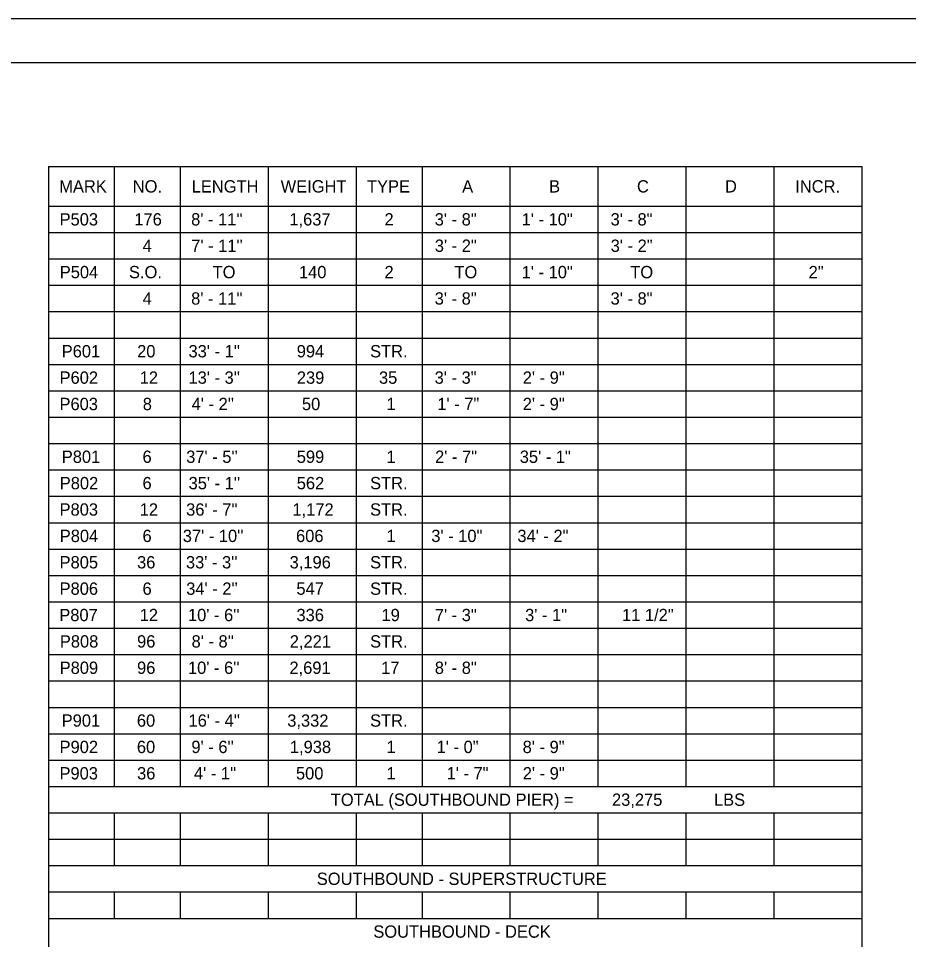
# Model space of a CAD drawing. Extents: x 1485751 to 1485785, y 230696.6 to 230718.6.
# Drawn here: x 1485763.32 to 1485773.44, y 230708.16 to 230718.64 of the extents above; entities that cross this region are included whole.
import ezdxf

# ---------------------------------------------------------------- set-up
doc = ezdxf.new("R2010")
doc.units = 0
for name, color, linetype in [('SH_Border', 7, 'Continuous'), ('SH_Cut_Line', 7, 'Continuous'), ('TX_P_Misc', 7, 'Continuous')]:
    doc.layers.add(name, color=color, linetype=linetype)

msp = doc.modelspace()

# ---------------------------------------------------------------- linework, layer by layer
at = {"layer": 'SH_Border'}
msp.add_lwpolyline([(1485753.033, 230718.141), (1485784.533, 230718.141), (1485784.533, 230697.141), (1485753.033, 230697.141)], close=True, dxfattribs=at)
at = {"layer": 'SH_Cut_Line'}
msp.add_lwpolyline([(1485751.033, 230718.641), (1485785.033, 230718.641), (1485785.033, 230696.641), (1485751.033, 230696.641)], close=True, dxfattribs=at)
at = {"layer": 'TX_P_Misc'}
for p, q in [((1485763.658, 230716.956), (1485772.908, 230716.956)), ((1485763.658, 230716.956), (1485763.658, 230698.806)), ((1485764.408, 230716.956), (1485764.408, 230709.906)), ((1485765.158, 230716.956), (1485765.158, 230709.906)), ((1485766.158, 230716.956), (1485766.158, 230709.906)), ((1485767.158, 230716.956), (1485767.158, 230709.906)), ((1485767.908, 230716.956), (1485767.908, 230709.906)), ((1485768.908, 230716.956), (1485768.908, 230709.906)), ((1485769.908, 230716.956), (1485769.908, 230709.906)), ((1485770.908, 230716.956), (1485770.908, 230709.906)), ((1485771.908, 230716.956), (1485771.908, 230709.906)), ((1485772.908, 230716.956), (1485772.908, 230698.806)), ((1485763.658, 230716.506), (1485772.908, 230716.506)), ((1485763.658, 230716.206), (1485772.908, 230716.206)), ((1485763.658, 230715.906), (1485772.908, 230715.906)), ((1485763.658, 230715.606), (1485772.908, 230715.606)), ((1485763.658, 230715.306), (1485772.908, 230715.306)), ((1485763.658, 230715.006), (1485772.908, 230715.006)), ((1485763.658, 230714.706), (1485772.908, 230714.706)), ((1485763.658, 230714.406), (1485772.908, 230714.406)), ((1485763.658, 230714.106), (1485772.908, 230714.106)), ((1485763.658, 230713.806), (1485772.908, 230713.806)), ((1485763.658, 230713.506), (1485772.908, 230713.506)), ((1485763.658, 230713.206), (1485772.908, 230713.206)), ((1485763.658, 230712.906), (1485772.908, 230712.906)), ((1485763.658, 230712.606), (1485772.908, 230712.606)), ((1485763.658, 230712.306), (1485772.908, 230712.306)), ((1485763.658, 230712.006), (1485772.908, 230712.006)), ((1485763.658, 230711.706), (1485772.908, 230711.706)), ((1485763.658, 230711.406), (1485772.908, 230711.406)), ((1485763.658, 230711.106), (1485772.908, 230711.106)), ((1485763.658, 230710.806), (1485772.908, 230710.806)), ((1485763.658, 230710.506), (1485772.908, 230710.506)), ((1485763.658, 230710.206), (1485772.908, 230710.206)), ((1485763.658, 230709.906), (1485772.908, 230709.906)), ((1485763.658, 230709.606), (1485772.908, 230709.606)), ((1485764.408, 230709.606), (1485764.408, 230709.006)), ((1485765.158, 230709.606), (1485765.158, 230709.006)), ((1485766.158, 230709.606), (1485766.158, 230709.006)), ((1485767.158, 230709.606), (1485767.158, 230709.006)), ((1485767.908, 230709.606), (1485767.908, 230709.006)), ((1485768.908, 230709.606), (1485768.908, 230709.006)), ((1485769.908, 230709.606), (1485769.908, 230709.006)), ((1485770.908, 230709.606), (1485770.908, 230709.006)), ((1485771.908, 230709.606), (1485771.908, 230709.006)), ((1485763.658, 230709.306), (1485772.908, 230709.306)), ((1485763.658, 230709.006), (1485772.908, 230709.006)), ((1485763.658, 230708.706), (1485772.908, 230708.706)), ((1485764.408, 230708.706), (1485764.408, 230708.406)), ((1485765.158, 230708.706), (1485765.158, 230708.406)), ((1485766.158, 230708.706), (1485766.158, 230708.406)), ((1485767.158, 230708.706), (1485767.158, 230708.406)), ((1485767.908, 230708.706), (1485767.908, 230708.406)), ((1485768.908, 230708.706), (1485768.908, 230708.406)), ((1485769.908, 230708.706), (1485769.908, 230708.406)), ((1485770.908, 230708.706), (1485770.908, 230708.406)), ((1485771.908, 230708.706), (1485771.908, 230708.406)), ((1485763.658, 230708.406), (1485772.908, 230708.406))]:
    msp.add_line(p, q, dxfattribs=at)

# ---------------------------------------------------------------- texts
for s, p in [('MARK', (1485763.782, 230716.661)), ('NO.', (1485764.618, 230716.661)), ('LENGTH', (1485765.288, 230716.661)), ('WEIGHT', (1485766.3, 230716.661)), ('TYPE', (1485767.282, 230716.661)), ('A', (1485768.364, 230716.661)), ('B', (1485769.353, 230716.661)), ('C', (1485770.352, 230716.661)), ('D', (1485771.353, 230716.661)), ('INCR.', (1485772.152, 230716.661)), ('P503', (1485763.786, 230716.286)), ('176', (1485764.636, 230716.286)), ("8' - 11''", (1485765.282, 230716.286)), ('1,637', (1485766.399, 230716.286)), ('2', (1485767.481, 230716.286)), ('3\' - 8"', (1485768.052, 230716.286)), ('1\' - 10"', (1485769.041, 230716.286)), ('3\' - 8"', (1485770.052, 230716.286)), ('4', (1485764.731, 230715.986)), ("7' - 11''", (1485765.283, 230715.986)), ('3\' - 2"', (1485768.053, 230715.986)), ('3\' - 2"', (1485770.053, 230715.986)), ('P504', (1485763.788, 230715.686)), ('S.O.', (1485764.575, 230715.686)), ('TO', (1485765.526, 230715.686)), ('140', (1485766.508, 230715.686)), ('2', (1485767.481, 230715.686)), ('TO', (1485768.276, 230715.686)), ('1\' - 10"', (1485769.041, 230715.686)), ('TO', (1485770.276, 230715.686)), (' 2"', (1485772.252, 230715.686)), ('4', (1485764.731, 230715.386)), ("8' - 11''", (1485765.282, 230715.386)), ('3\' - 8"', (1485768.052, 230715.386)), ('3\' - 8"', (1485770.052, 230715.386)), ('P601', (1485763.81, 230714.786)), ('20', (1485764.668, 230714.786)), ("33' - 1''", (1485765.252, 230714.786)), ('994', (1485766.483, 230714.786)), ('STR.', (1485767.317, 230714.786)), ('P602', (1485763.786, 230714.486)), ('12', (1485764.697, 230714.486)), ("13' - 3''", (1485765.252, 230714.486)), ('239', (1485766.484, 230714.486)), ('35', (1485767.418, 230714.486)), ('3\' - 3"', (1485768.051, 230714.486)), ('2\' - 9"', (1485769.053, 230714.486)), ('P603', (1485763.785, 230714.186)), ('8', (1485764.732, 230714.186)), ("4' - 2''", (1485765.288, 230714.186)), ('50', (1485766.542, 230714.186)), ('1', (1485767.504, 230714.186)), ('1\' - 7"', (1485768.082, 230714.186)), ('2\' - 9"', (1485769.053, 230714.186)), ('P801', (1485763.811, 230713.586)), ('6', (1485764.729, 230713.586)), ("37' - 5''", (1485765.226, 230713.586)), ('599', (1485766.483, 230713.586)), ('1', (1485767.504, 230713.586)), ('2\' - 7"', (1485768.056, 230713.586)), ('35\' - 1"', (1485769.019, 230713.586)), ('P802', (1485763.788, 230713.286)), ('6', (1485764.729, 230713.286)), ("35' - 1''", (1485765.253, 230713.286)), ('562', (1485766.483, 230713.286)), ('STR.', (1485767.317, 230713.286)), ('P803', (1485763.786, 230712.986)), ('12', (1485764.697, 230712.986)), ("36' - 7''", (1485765.225, 230712.986)), ('1,172', (1485766.434, 230712.986)), ('STR.', (1485767.317, 230712.986)), ('P804', (1485763.788, 230712.686)), ('6', (1485764.729, 230712.686)), ("37' - 10''", (1485765.187, 230712.686)), ('606', (1485766.475, 230712.686)), ('1', (1485767.504, 230712.686)), ('3\' - 10"', (1485768.013, 230712.686)), ('34\' - 2"', (1485768.992, 230712.686)), ('P805', (1485763.786, 230712.386)), ('36', (1485764.667, 230712.386)), ("33' - 3''", (1485765.223, 230712.386)), ('3,196', (1485766.402, 230712.386)), ('STR.', (1485767.317, 230712.386)), ('P806', (1485763.786, 230712.086)), ('6', (1485764.729, 230712.086)), ("34' - 2''", (1485765.226, 230712.086)), ('547', (1485766.479, 230712.086)), ('STR.', (1485767.317, 230712.086)), ('P807', (1485763.783, 230711.786)), ('12', (1485764.697, 230711.786)), ("10' - 6''", (1485765.246, 230711.786)), ('336', (1485766.48, 230711.786)), ('19', (1485767.447, 230711.786)), ('7\' - 3"', (1485768.053, 230711.786)), ('3\' - 1"', (1485769.08, 230711.786)), (' 11 1/2"', (1485770.13, 230711.786)), ('P808', (1485763.789, 230711.486)), ('96', (1485764.667, 230711.486)), ("8' - 8''", (1485765.287, 230711.486)), ('2,221', (1485766.404, 230711.486)), ('STR.', (1485767.317, 230711.486)), ('P809', (1485763.787, 230711.186)), ('96', (1485764.667, 230711.186)), ("10' - 6''", (1485765.246, 230711.186)), ('2,691', (1485766.4, 230711.186)), ('17', (1485767.443, 230711.186)), ('8\' - 8"', (1485768.053, 230711.186)), ('P901', (1485763.81, 230710.586)), ('60', (1485764.665, 230710.586)), ("16' - 4''", (1485765.252, 230710.586)), ('3,332', (1485766.375, 230710.586)), ('STR.', (1485767.317, 230710.586)), ('P902', (1485763.786, 230710.286)), ('60', (1485764.665, 230710.286)), ("9' - 6''", (1485765.285, 230710.286)), ('1,938', (1485766.405, 230710.286)), ('1', (1485767.504, 230710.286)), ('1\' - 0"', (1485768.074, 230710.286)), ('8\' - 9"', (1485769.052, 230710.286)), ('P903', (1485763.785, 230709.986)), ('36', (1485764.667, 230709.986)), ("4' - 1''", (1485765.314, 230709.986)), ('500', (1485766.474, 230709.986)), ('1', (1485767.504, 230709.986)), ('1\' - 7"', (1485768.187, 230709.986)), ('2\' - 9"', (1485769.053, 230709.986)), ('TOTAL (SOUTHBOUND PIER) =', (1485766.87, 230709.686)), ('23,275', (1485770.068, 230709.686)), ('LBS', (1485771.228, 230709.686)), ('SOUTHBOUND - SUPERSTRUCTURE', (1485766.711, 230708.786)), ('SOUTHBOUND - DECK', (1485767.354, 230708.186))]:
    msp.add_text(s, height=0.14, dxfattribs=at).set_placement(p)

doc.saveas('drawing.dxf')
